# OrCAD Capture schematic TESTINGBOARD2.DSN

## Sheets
1 Comunication: size A4
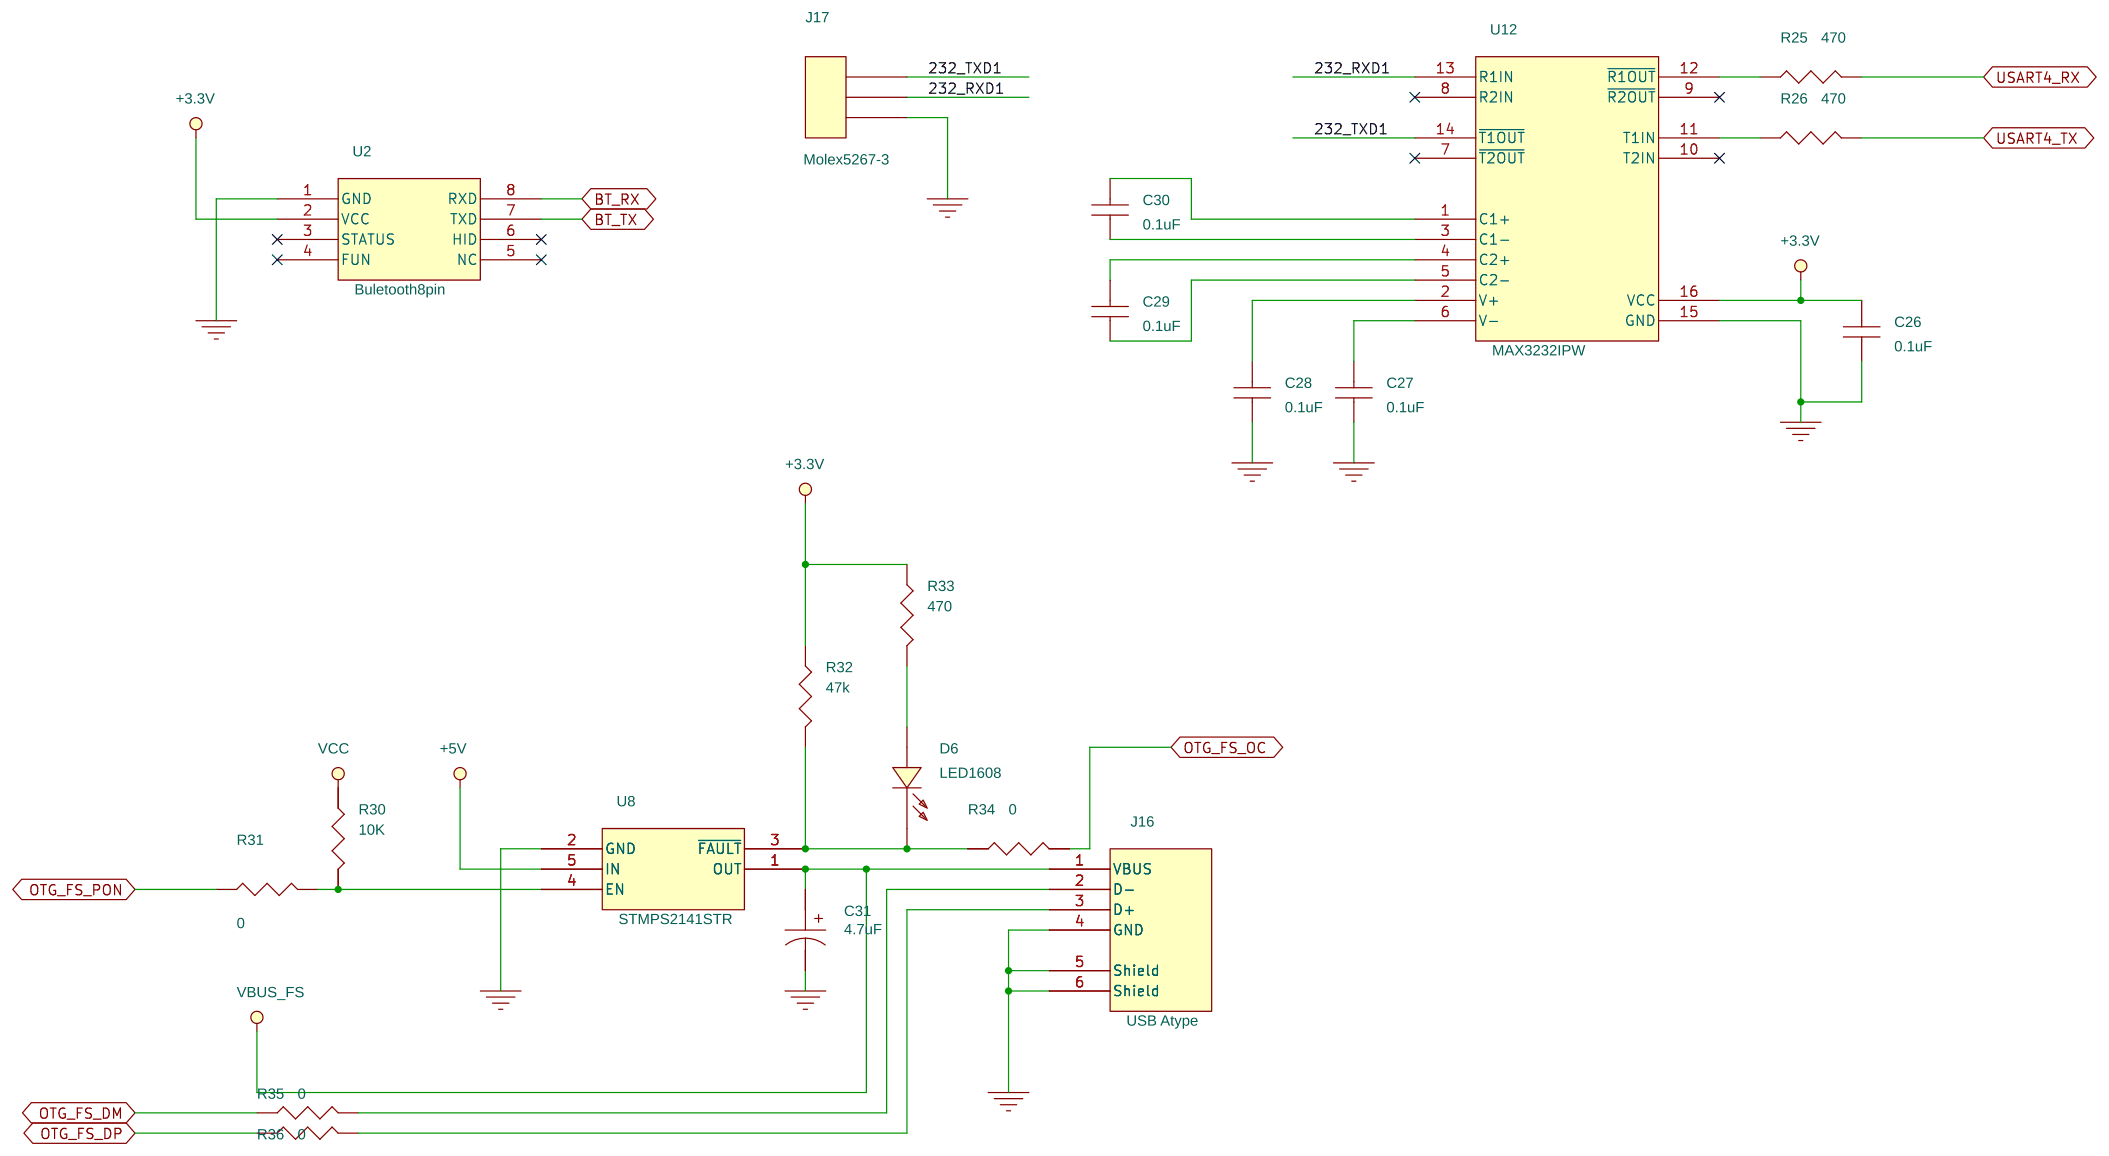
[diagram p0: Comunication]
2 Dcmotor: size A4
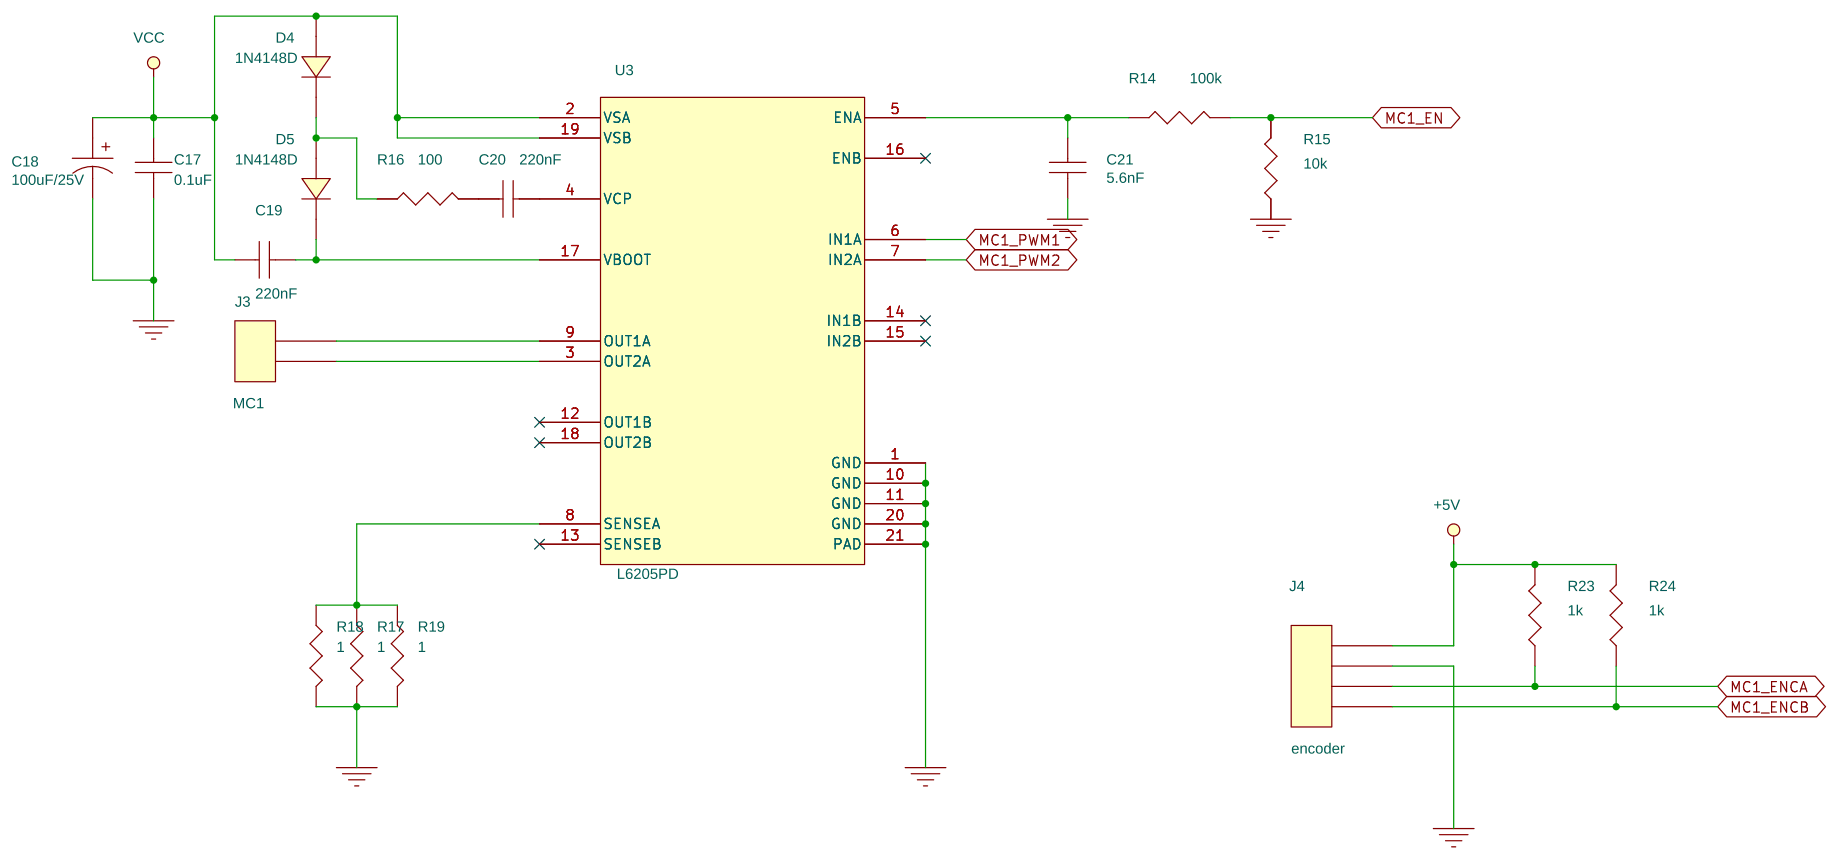
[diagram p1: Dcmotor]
3 Main: size A4
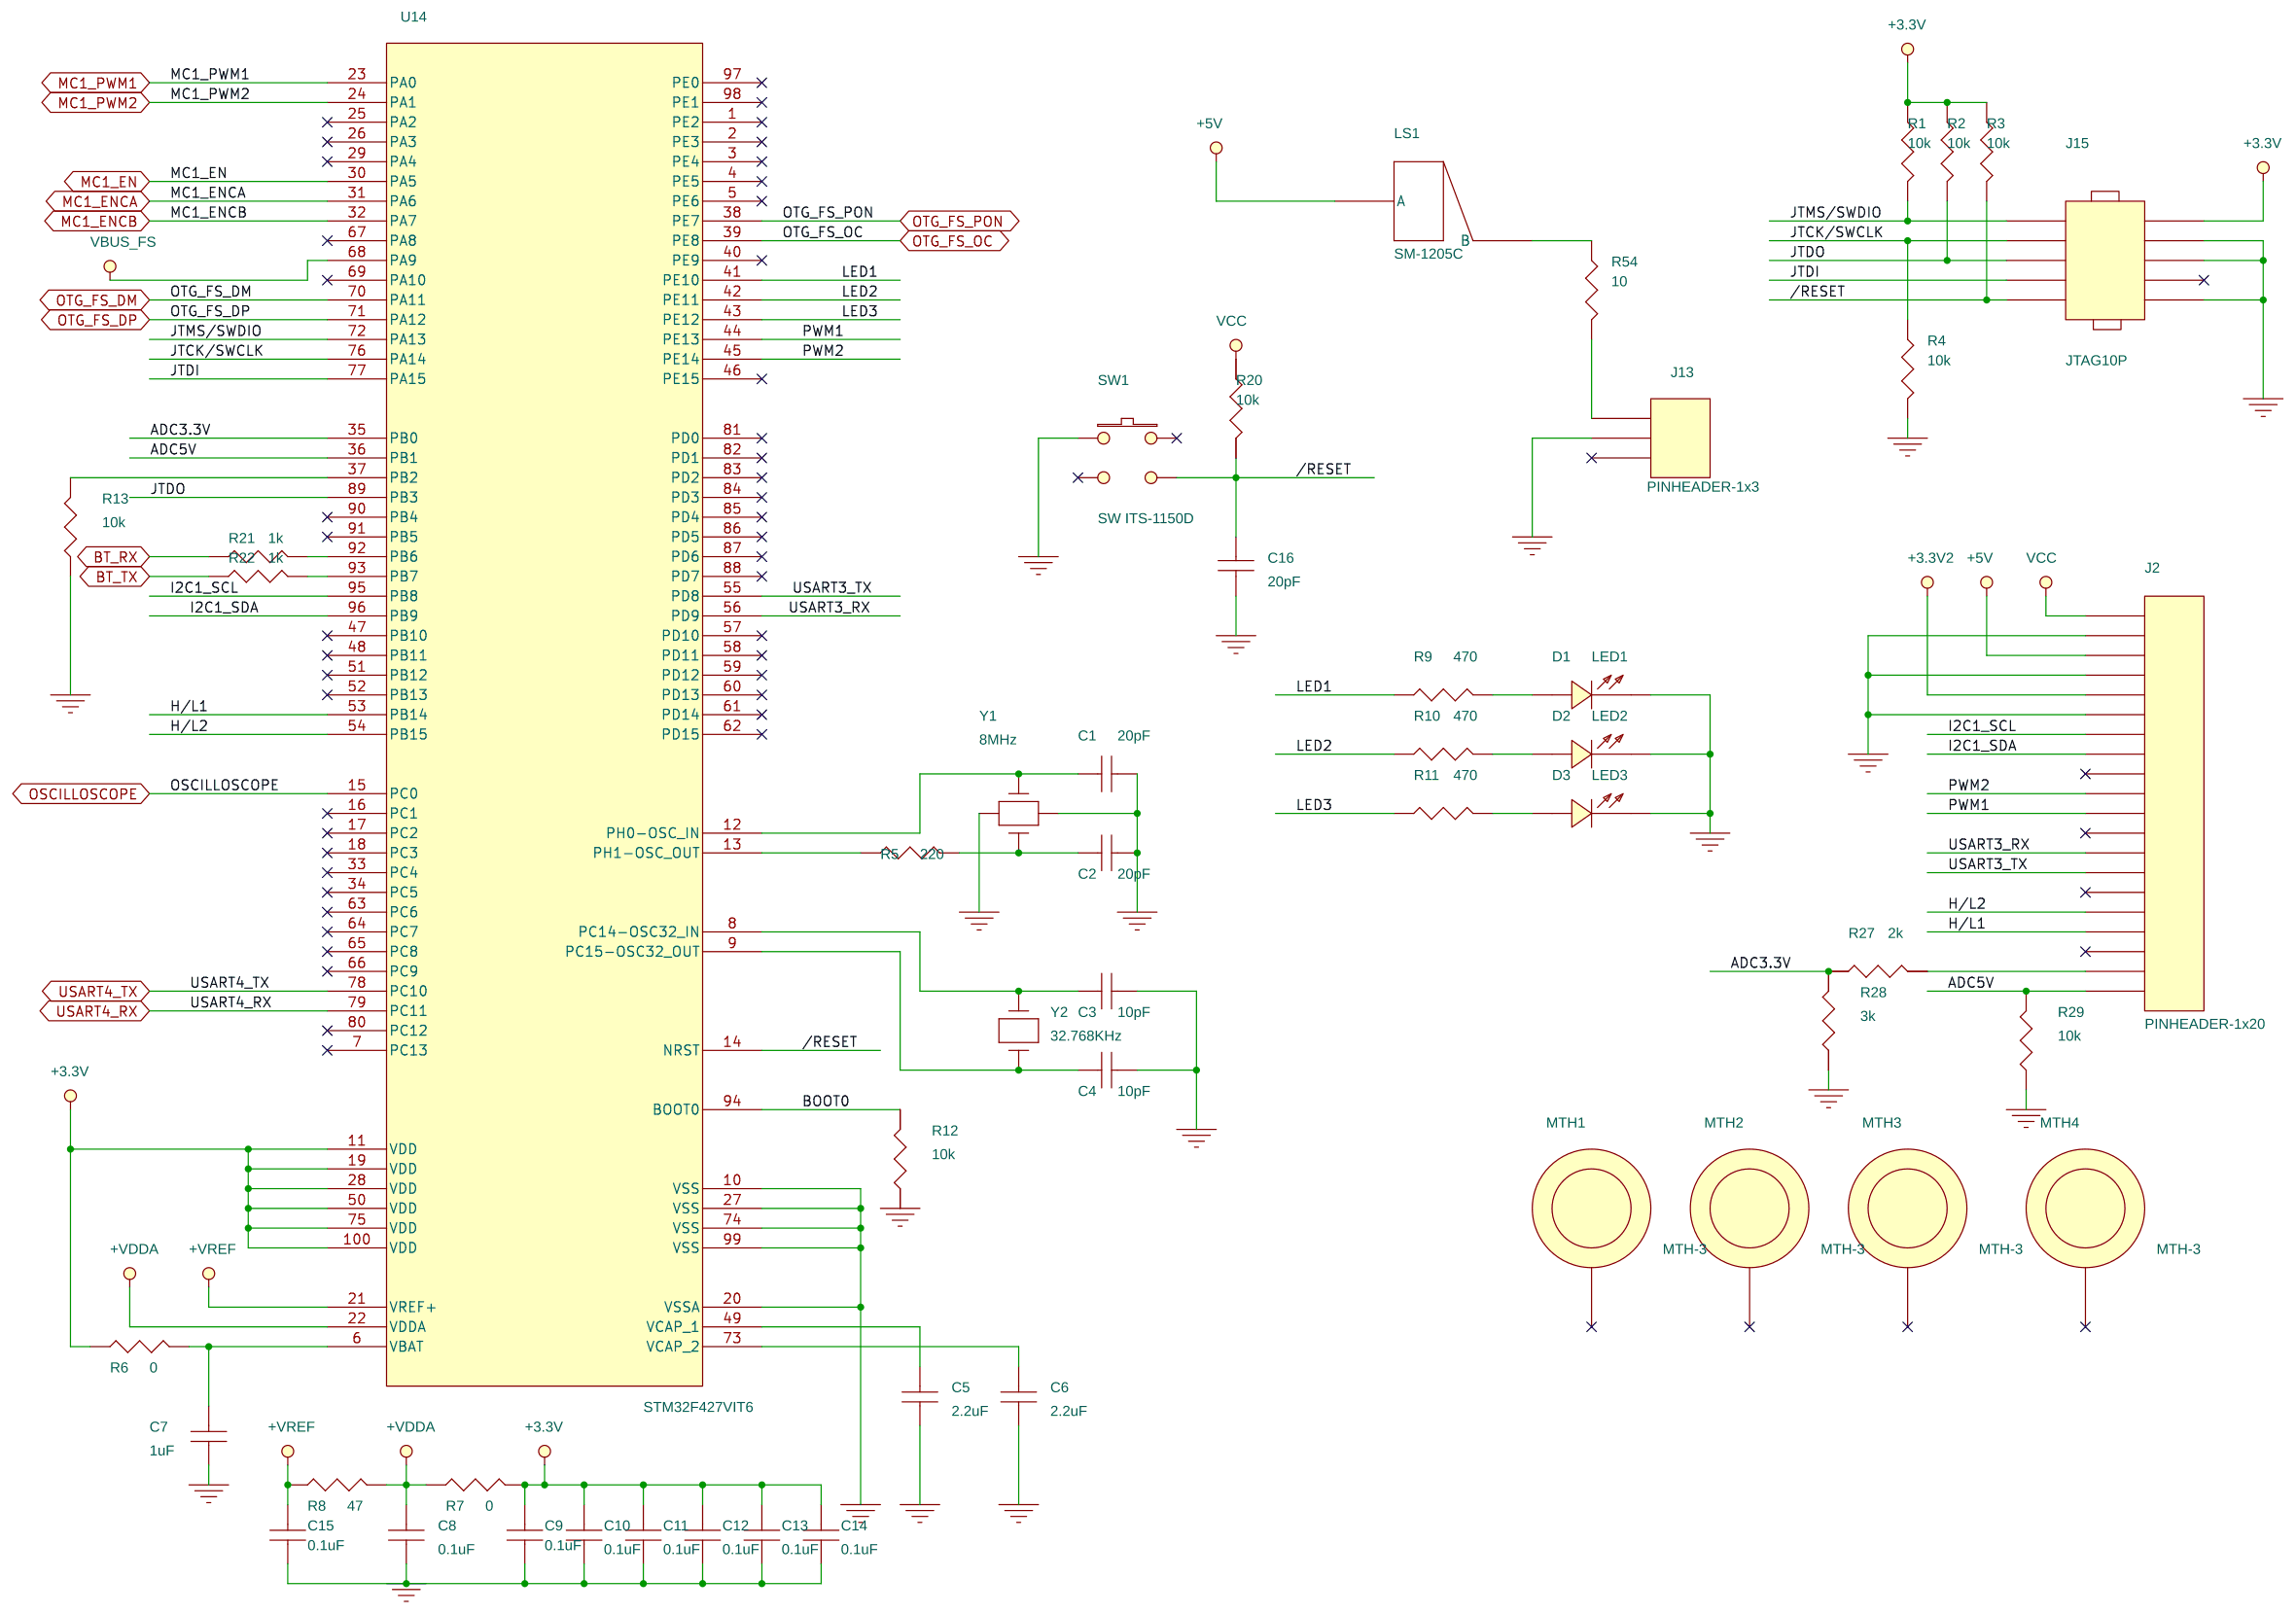
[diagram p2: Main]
4 Oscilloscope: size A4
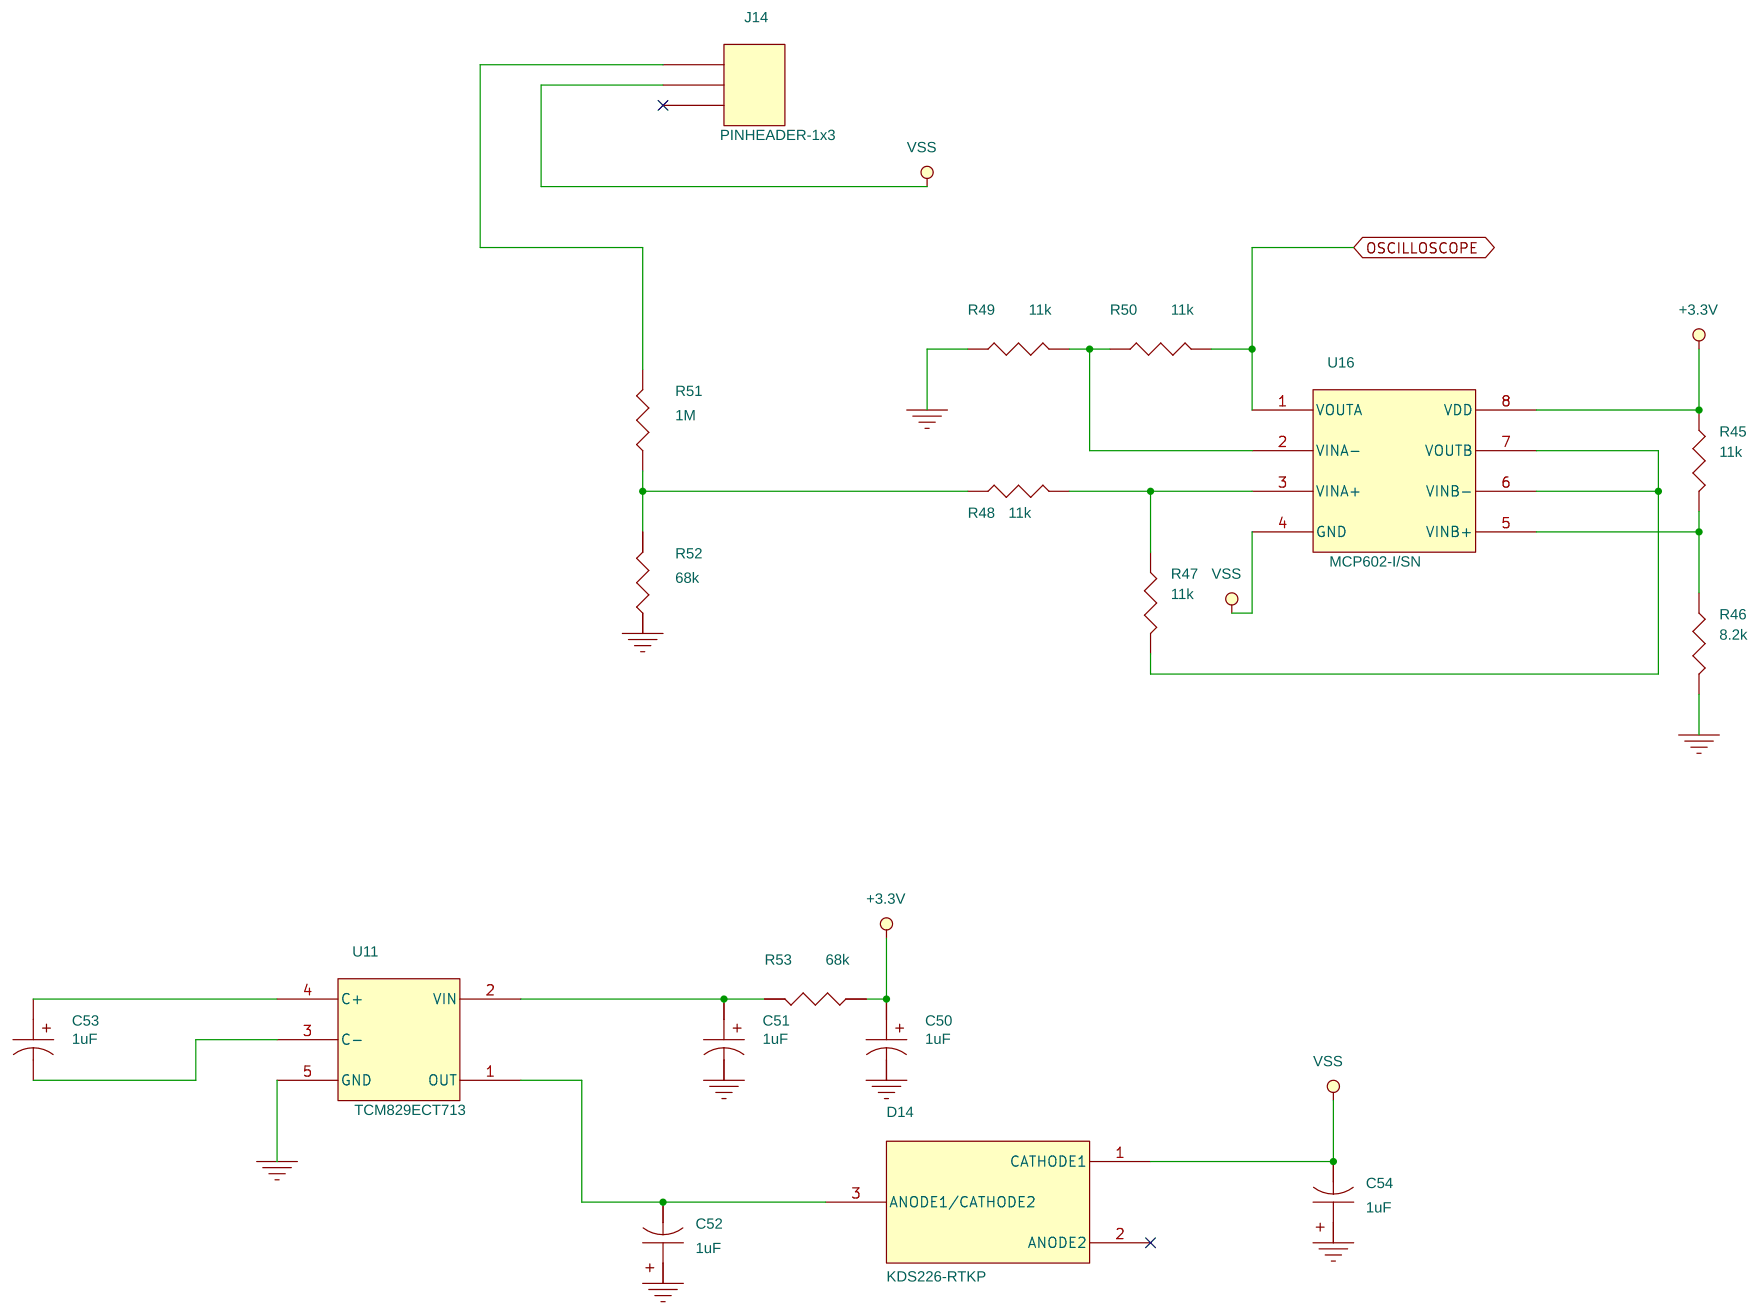
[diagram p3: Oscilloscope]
5 Power: size A4
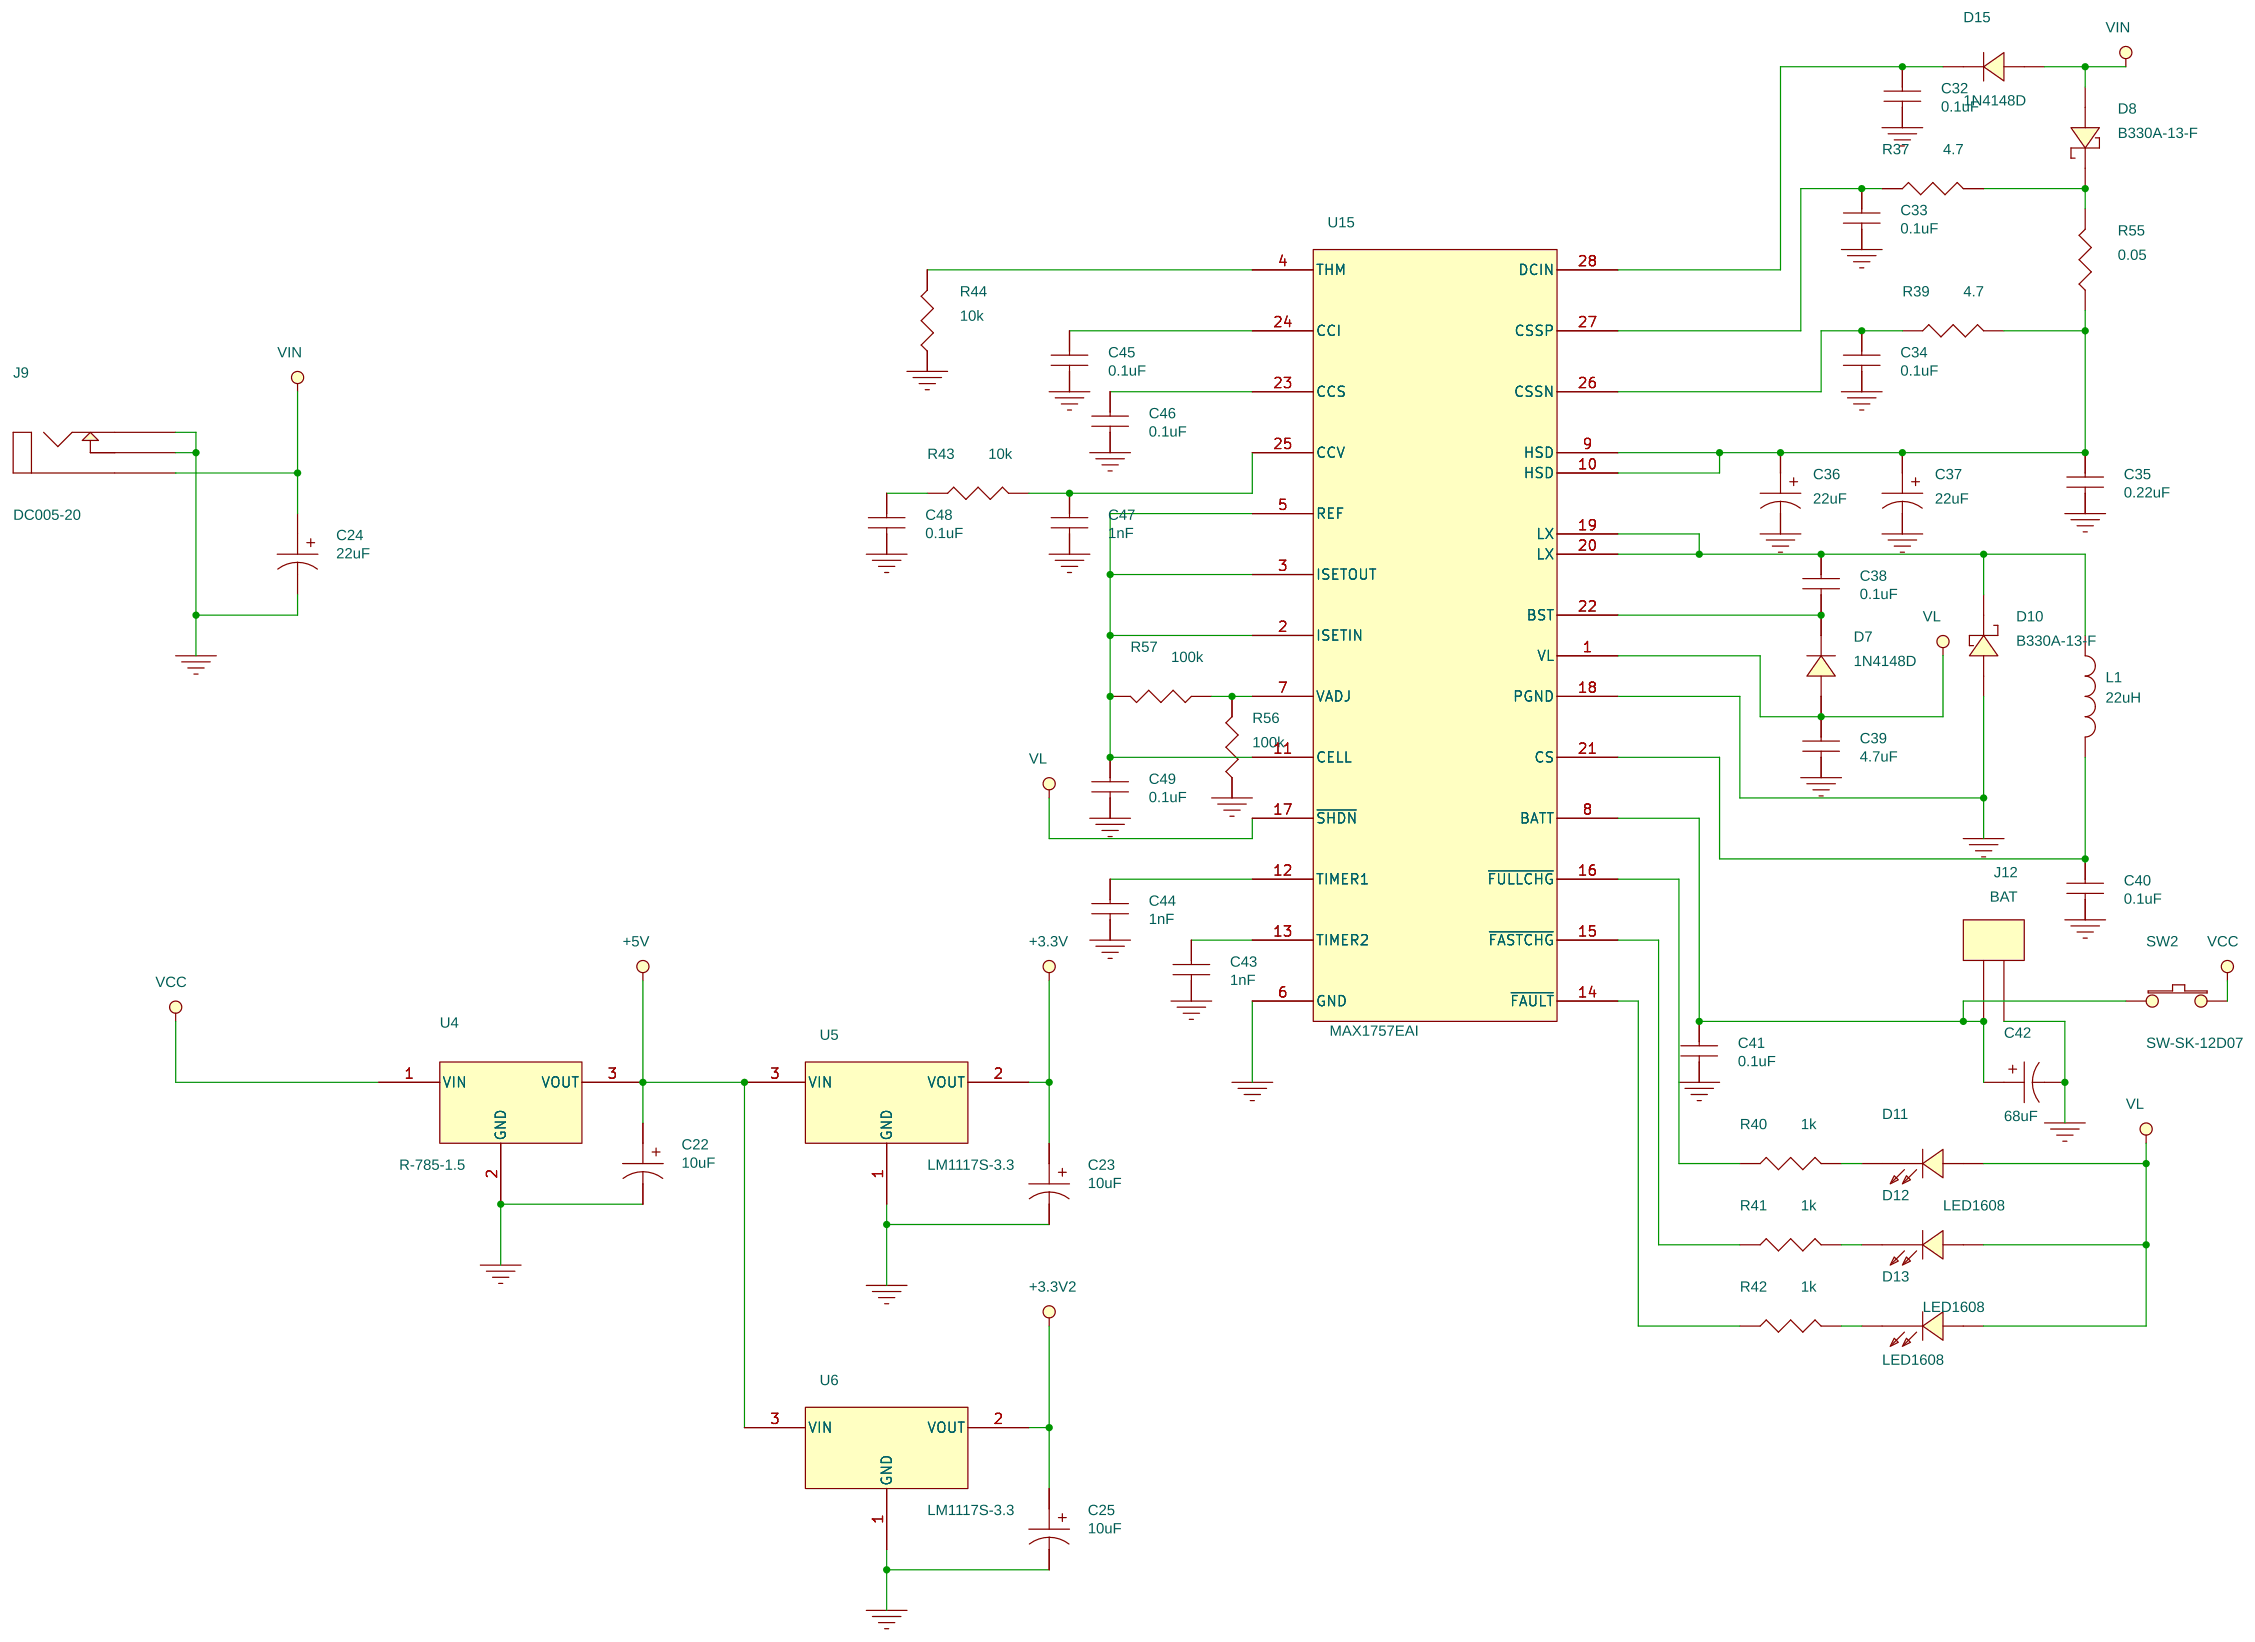
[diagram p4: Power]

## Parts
sheet Comunication
C26  0.1uF  [C1608]
C27  0.1uF  [C1608]
C28  0.1uF  [C1608]
C29  0.1uF  [C1608]
C30  0.1uF  [C1608]
C31  4.7uF  [Tantal_B]
D6  LED1608  [LED1608]
J16  USB Atype  [USB/A]
J17  Molex5267-3  [Molex5267-3]
R25  470  [R1608]
R26  470  [R1608]
R30  10K  [R1608]
R31  0  [R1608]
R32  47k  [R1608]
R33  470  [R1608]
R34  0  [R1608]
R35  0  [R1608]
R36  0  [R1608]
U2  Buletooth8pin  [Buletooth8pin]
U8  STMPS2141STR  [SOT-23-5]
U12  MAX3232IPW  [TSSOP16]
sheet Dcmotor
C17  0.1uF  [C2012]
C18  100uF/25V  [CE6.3x6]
C19  220nF  [C2012]
C20  220nF  [C2012]
C21  5.6nF  [C2012]
D4  1N4148D  [SOD-80]
D5  1N4148D  [SOD-80]
J3  MC1  [Molex5267-2]
J4  encoder  [Molex5267-4]
R14  100k  [R2012]
R15  10k  [R2012]
R16  100  [R2012]
R17  1  [R2512]
R18  1  [R2512]
R19  1  [R2512]
R23  1k  [R2012]
R24  1k  [R2012]
U3  L6205PD  [L6205PD]
sheet Main
C1  20pF  [C1608]
C2  20pF  [C1608]
C3  10pF  [C1608]
C4  10pF  [C1608]
C5  2.2uF  [C1608]
C6  2.2uF  [C1608]
C7  1uF  [C1608]
C8  0.1uF  [C1608]
C9  0.1uF  [C1608]
C10  0.1uF  [C1608]
C11  0.1uF  [C1608]
C12  0.1uF  [C1608]
C13  0.1uF  [C1608]
C14  0.1uF  [C1608]
C15  0.1uF  [C1608]
C16  20pF  [C1608]
D1  LED1  [LED1608]
D2  LED2  [LED1608]
D3  LED3  [LED1608]
J2  PINHEADER-1x20  [PINHEADER-1x20]
J13  PINHEADER-1x3  [PINHEADER-1x3]
J15  JTAG10P  [BOXHEADER-5x2-2mm]
LS1  SM-1205C
MTH1  MTH-3  [MTH-3]
MTH2  MTH-3  [MTH-3]
MTH3  MTH-3  [MTH-3]
MTH4  MTH-3  [MTH-3]
R1  10k  [R1608]
R2  10k  [R1608]
R3  10k  [R1608]
R4  10k  [R1608]
R5  220  [R1608]
R6  0  [R1608]
R7  0  [R1608]
R8  47  [R1608]
R9  470  [R1608]
R10  470  [R1608]
R11  470  [R1608]
R12  10k  [R1608]
R13  10k  [R1608]
R20  10k  [R1608]
R21  1k  [R1608]
R22  1k  [R1608]
R27  2k  [R1608]
R28  3k  [R1608]
R29  10k  [R1608]
R54  10  [R1608]
SW1  SW ITS-1150D  [SW-ITS-1150D]
U14  STM32F427VIT6  [QFP100/14x14/0.5]
Y1  8MHz  [CRYSTAL3x5]
Y2  32.768KHz  [CRYSTAL3.2x1.5]
sheet Oscilloscope
C50  1uF  [Tantal_B]
C51  1uF  [Tantal_B]
C52  1uF  [Tantal_B]
C53  1uF  [Tantal_B]
C54  1uF  [Tantal_B]
D14  KDS226-RTKP  [SOT-23-3]
J14  PINHEADER-1x3  [PINHEADER-1x3]
R45  11k  [R1608]
R46  8.2k  [R1608]
R47  11k  [R1608]
R48  11k  [R1608]
R49  11k  [R1608]
R50  11k  [R1608]
R51  1M  [R1608]
R52  68k  [R1608]
R53  68k  [R1608]
U11  TCM829ECT713  [SOT-23-5]
U16  MCP602-I/SN  [SOIC8]
sheet Power
C22  10uF  [Tantal_B]
C23  10uF  [Tantal_B]
C24  22uF  [CE6.3x6]
C25  10uF  [Tantal_B]
C32  0.1uF  [C1608]
C33  0.1uF  [C1608]
C34  0.1uF  [C1608]
C35  0.22uF  [C1608]
C36  22uF  [Tantal_B]
C37  22uF  [Tantal_B]
C38  0.1uF  [C1608]
C39  4.7uF  [C1608]
C40  0.1uF  [C1608]
C41  0.1uF  [C1608]
C42  68uF  [Tantal_B]
C43  1nF  [C1608]
C44  1nF  [C1608]
C45  0.1uF  [C1608]
C46  0.1uF  [C1608]
C47  1nF  [C1608]
C48  0.1uF  [C1608]
C49  0.1uF  [C1608]
D7  1N4148D  [SOD-80]
D8  B330A-13-F  [SMA]
D10  B330A-13-F  [SMA]
D11  LED1608  [LED1608]
D12  LED1608  [LED1608]
D13  LED1608  [LED1608]
D15  1N4148D  [SOD-80]
J9  DC005-20
J12  BAT  [Molex5267-2]
L1  22uH  [CDRH104RNP-220NC]
R37  4.7  [R1608]
R39  4.7  [R1608]
R40  1k  [R1608]
R41  1k  [R1608]
R42  1k  [R1608]
R43  10k  [R1608]
R44  10k  [R1608]
R55  0.05  [R5025]
R56  100k  [R1608]
R57  100k  [R1608]
SW2  SW-SK-12D07  [SW-SK-12D07]
U4  R-785-1.5  [R-785-1.5]
U5  LM1117S-3.3  [SOT-223]
U6  LM1117S-3.3  [SOT-223]
U15  MAX1757EAI  [MAX1757EAI]

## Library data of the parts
C1-C16 C26-C30 C32-C35 C38-C41 C43-C49 = C1608
C22 C23 C25 C31 C36 C37 C42 C50-C54 = Tantal_B
D1-D3 D6 D11-D13 = LED1608
J16 = USB_Atype
J17 = Molex5267-3
R1-R13 R20-R22 R25-R37 R39-R54 R56 R57 = R1608
U2 = Buletooth8pin
U8 = STMPS2141STR
U12 = MAX3232IPW
C17 C19-C21 = C2012
C18 C24 = CE6.3x6
D4 D5 D7 D15 = 1N4148D
J3 J12 = Molex5267-2
J4 = Molex5267-4
R14-R16 R23 R24 = R2012
R17-R19 = R2512
U3 = L6205PD
J2 = PINHEADER-1x20
J13 J14 = PINHEADER-1x3
J15 = JTAG10P
LS1 = SM-1205C
MTH1-MTH4 = MTH-3
SW1 = SW_ITS-1150D
U14 = STM32F427VIT6
Y1 = CRYSTAL3x5
Y2 = CRYSTAL3.2x1.5
D14 = KDS226-RTKP
U11 = TCM829ECT713
U16 = MCP602-I_SN
D8 D10 = B330A-13-F
J9 = DC005-20
L1 = CDRH104RNP-220NC
R55 = WSL2010R0500FEK
SW2 = SW-SK-12D07
U4 = R-785-1.5
U5 U6 = LM1117S-3.3
U15 = MAX1757EAI

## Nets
+3.3V: C9.2 C10.2 C11.2 C12.2 C13.2 C14.2 C23.1 C26.2 C50.1 J15.1 R1.1 R2.1 R3.1 R6.1 R7.2 R20.1 R30.1 R32.1 R33.1 R45.1 R53.1 U2.2(VCC) U5.2(VOUT) U12.16(VCC) U14.11(VDD) U14.19(VDD) U14.28(VDD) U14.50(VDD) U14.75(VDD) U14.100(VDD) U16.8(VDD)
+3.3V2: C25.1 J2.5 U6.2(VOUT)
+5V: C22.1 J2.3 J4.1 LS1.1(A) R23.2 R24.2 U4.3(VOUT) U5.3(VIN) U6.3(VIN) U8.5(IN)
+VDDA: C8.2 R7.1 R8.2 U14.22(VDDA)
GND: C1.2 C2.2 C3.2 C4.2 C5.1 C6.1 C7.1 C8.1 C9.1 C10.1 C11.1 C12.1 C13.1 C14.1 C15.1 C16.2 C17.2 C18.2 C21.2 C22.2 C23.2 C24.2 C25.2 C26.1 C27.1 C28.1 C31.2 C32.2 C33.2 C34.2 C35.2 C36.2 C37.2 C39.2 C40.2 C41.2 C42.2 C43.2 C44.2 C45.2 C46.2 C47.2 C48.2 C49.2 C50.2 C51.2 C52.1 C54.1 D1.1(CATHODE) D2.1(CATHODE) D3.1(CATHODE) D10.1(ANODE) J2.2 J2.4 J2.6 J4.2 J9.2 J9.3 J12.2 J13.2 J15.3 J15.5 J15.9 J16.4(GND) J16.5(Shield) J16.6(Shield) J17.3 R4.2 R12.1 R13.1 R15.1 R17.2 R18.2 R19.2 R28.1 R29.1 R44.1 R46.2 R49.1 R52.1 R56.1 SW1.1 U2.1(GND) U3.1(GND) U3.10(GND) U3.11(GND) U3.20(GND) U3.21(PAD) U4.2(GND) U5.1(GND) U6.1(GND) U8.2(GND) U11.5(GND) U12.15(GND) U14.10(VSS) U14.20(VSSA) U14.27(VSS) U14.74(VSS) U14.99(VSS) U15.6(GND) U15.18(PGND) Y1.2 Y1.4
VBUS_FS: C31.1 J16.1(VBUS) U8.1(OUT) U14.68(PA9)
VCC: C17.1 C18.1 C19.1 D4.2(A) J2.1 SW2.2 U3.2(VSA) U3.19(VSB) U4.1(VIN)
VIN: C24.1 D8.1(ANODE) D15.2(A) J9.1
VSS: C54.2 D14.1(CATHODE1) J14.2 U16.4(GND)
232_RXD1: J17.2 U12.13(R1IN)
232_TXD1: J17.1 U12.14(~{T1OUT})
+VREF: C15.2 R8.1 U14.21(VREF+)
/RESET: C16.1 J15.10 R3.2 R20.2 SW1.4 U14.14(NRST)
ADC3.3V: R27.1 R28.2 U14.35(PB0)
ADC5V: J2.20 R29.2 U14.36(PB1)
BOOT0: R12.2 U14.94(BOOT0)
BT_RX: R21.1 U2.8(RXD)
BT_TX: R22.1 U2.7(TXD)
H/L1: J2.17 U14.53(PB14)
H/L2: J2.16 U14.54(PB15)
I2C1_SCL: J2.7 U14.95(PB8)
I2C1_SDA: J2.8 U14.96(PB9)
JTCK/SWCLK: J15.4 R4.1 U14.76(PA14)
JTDI: J15.8 U14.77(PA15)
JTDO: J15.6 R2.2 U14.89(PB3)
JTMS/SWDIO: J15.2 R1.2 U14.72(PA13)
LED1: R9.1 U14.41(PE10)
LED2: R10.1 U14.42(PE11)
LED3: R11.1 U14.43(PE12)
MC1_EN: R14.2 R15.2 U14.30(PA5)
MC1_ENCA: J4.3 R23.1 U14.31(PA6)
MC1_ENCB: J4.4 R24.1 U14.32(PA7)
MC1_PWM1: U3.6(IN1A) U14.23(PA0)
MC1_PWM2: U3.7(IN2A) U14.24(PA1)
OSCILLOSCOPE: R50.2 U14.15(PC0) U16.1(VOUTA)
OTG_FS_DM: R35.1 U14.70(PA11)
OTG_FS_DP: R36.1 U14.71(PA12)
OTG_FS_OC: R34.2 U14.39(PE8)
OTG_FS_PON: R31.1 U14.38(PE7)
PWM1: J2.11 U14.44(PE13)
PWM2: J2.10 U14.45(PE14)
USART3_RX: J2.13 U14.56(PD9)
USART3_TX: J2.14 U14.55(PD8)
USART4_RX: R25.2 U14.79(PC11)
USART4_TX: R26.2 U14.78(PC10)
VL: C39.1 D7.2(A) D11.2(ANODE) D12.2(ANODE) D13.2(ANODE) U15.1(VL) U15.17(~{SHDN})
N32482: J2.19 R27.2
N34484: C1.1 U14.12(PH0-OSC_IN) Y1.3
N34518: R5.1 U14.13(PH1-OSC_OUT)
N34522: C2.1 R5.2 Y1.1
N34926: C3.1 U14.8(PC14-OSC32_IN) Y2.2
N34938: C4.1 U14.9(PC15-OSC32_OUT) Y2.1
N35545: C5.2 U14.49(VCAP_1)
N35552: C6.2 U14.73(VCAP_2)
N35968: C7.2 R6.2 U14.6(VBAT)
N38233: D1.2(ANODE) R9.2
N38289: D2.2(ANODE) R10.2
N38293: D3.2(ANODE) R11.2
N43889: R13.2 U14.37(PB2)
N65898: R17.1 R18.1 R19.1 U3.8(SENSEA)
N66010: C19.2 D5.1(K) U3.17(VBOOT)
N66030: J3.1 U3.9(OUT1A)
N66050: J3.2 U3.3(OUT2A)
N66074: C21.1 R14.1 U3.5(ENA)
N66226: D4.1(K) D5.2(A) R16.1
N70838: C27.2 U12.6(V-)
N70847: C28.2 U12.2(V+)
N70906: C30.2 U12.1(C1+)
N70918: C30.1 U12.3(C1-)
N70922: C29.2 U12.4(C2+)
N70929: C29.1 U12.5(C2-)
N71046: R25.1 U12.12(~{R1OUT})
N71050: R26.1 U12.11(T1IN)
N72193: R30.2 R31.2 U8.4(EN)
N72465: D6.2(ANODE) R33.2
N72484: D6.1(CATHODE) R32.2 R34.1 U8.3(~{FAULT})
N72793: J16.2(D-) R35.2
N72808: J16.3(D+) R36.2
N74285: C32.1 D15.1(K) U15.28(DCIN)
N74550: D8.2(CATHODE) R37.2 R55.2
N74644: C33.1 R37.1 U15.27(CSSP)
N74792: C35.1 C36.1 C37.1 R39.2 R55.1 U15.9(HSD) U15.10(HSD)
N74837: C34.1 R39.1 U15.26(CSSN)
N75301: C38.1 D10.2(CATHODE) L1.1 U15.19(LX) U15.20(LX)
N76667: C38.2 D7.1(K) U15.22(BST)
N77321: C40.1 L1.2 U15.21(CS)
N77403: C41.1 C42.1 J12.1 SW2.1 U15.8(BATT)
N77876: R40.1 U15.16(~{FULLCHG})
N78139: D11.1(CATHODE) R40.2
N78147: R41.1 U15.15(~{FASTCHG})
N78159: R42.1 U15.14(~{FAULT})
N78171: D12.1(CATHODE) R41.2
N78175: D13.1(CATHODE) R42.2
N78541: C44.1 U15.12(TIMER1)
N78550: C43.1 U15.13(TIMER2)
N78770: C46.1 U15.23(CCS)
N78774: C45.1 U15.24(CCI)
N78782: C47.1 R43.2 U15.25(CCV)
N78979: C48.1 R43.1
N78991: C49.1 R57.2 U15.2(ISETIN) U15.3(ISETOUT) U15.5(REF) U15.11(CELL)
N81087: R44.2 U15.4(THM)
N81312: R45.2 R46.1 U16.5(VINB+)
N81338: R47.2 U16.6(VINB-) U16.7(VOUTB)
N81382: R47.1 R48.2 U16.3(VINA+)
N81496: R49.2 R50.1 U16.2(VINA-)
N81711: R48.1 R51.1 R52.2
N81745: J14.1 R51.2
N81994: C51.1 R53.2 U11.2(VIN)
N82070: C52.2 D14.3(ANODE1/CATHODE2) U11.1(OUT)
N82187: C53.1 U11.4(C+)
N82191: C53.2 U11.3(C-)
N84675: LS1.2(B) R54.1
N86837: J13.1 R54.2
N129621: C20.2 U3.4(VCP)
N129623: C20.1 R16.2
N130073: R56.2 R57.1 U15.7(VADJ)
N136385: R22.2 U14.93(PB7)
N136429: R21.2 U14.92(PB6)

Not connected (* = marked no-connect by the designer): D14 2(ANODE2)*; J2 9* 12* 15* 18*; J13 3*; J14 3*; J15 7*; MTH1 1(GND)*; MTH2 1(GND)*; MTH3 1(GND)*; MTH4 1(GND)*; SW1 2* 3*; U2 3(STATUS)* 4(FUN)* 5(NC)* 6(HID)*; U3 12(OUT1B)* 13(SENSEB)* 14(IN1B)* 15(IN2B)* 16(ENB)* 18(OUT2B)*; U12 7(~{T2OUT})* 8(R2IN)* 9(~{R2OUT})* 10(T2IN)*; U14 1(PE2)* 2(PE3)* 3(PE4)* 4(PE5)* 5(PE6)* 7(PC13)* 16(PC1)* 17(PC2)* 18(PC3)* 25(PA2)* 26(PA3)* 29(PA4)* 33(PC4)* 34(PC5)* 40(PE9)* 46(PE15)* 47(PB10)* 48(PB11)* 51(PB12)* 52(PB13)* 57(PD10)* 58(PD11)* 59(PD12)* 60(PD13)* 61(PD14)* 62(PD15)* 63(PC6)* 64(PC7)* 65(PC8)* 66(PC9)* 67(PA8)* 69(PA10)* 80(PC12)* 81(PD0)* 82(PD1)* 83(PD2)* 84(PD3)* 85(PD4)* 86(PD5)* 87(PD6)* 88(PD7)* 90(PB4)* 91(PB5)* 97(PE0)* 98(PE1)*
